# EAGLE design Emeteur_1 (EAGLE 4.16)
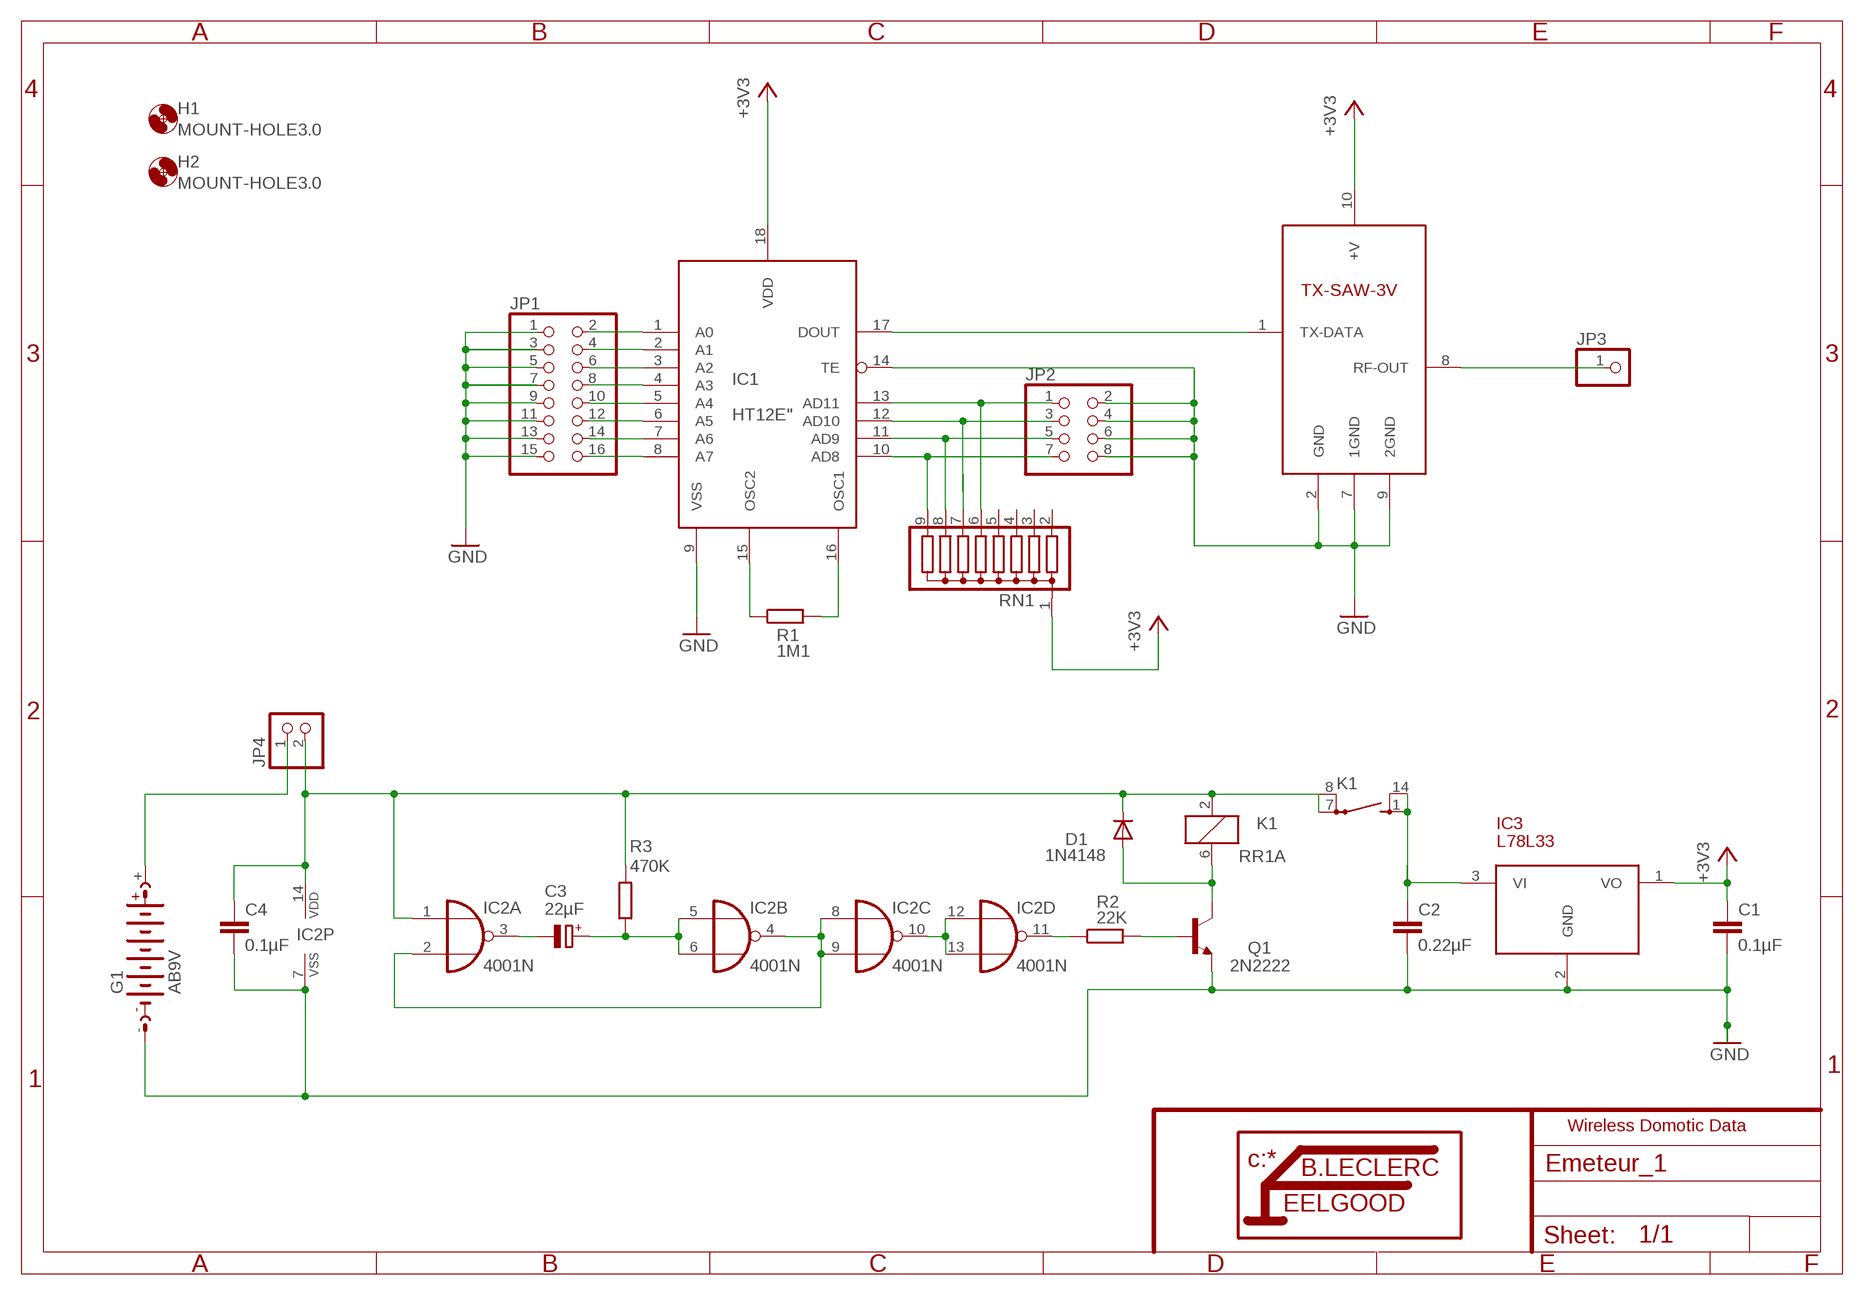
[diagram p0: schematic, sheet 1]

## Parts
C1  0.1µF  C-EU102-043X133  [C102-043X133]
C2  0.22µF  C-EU102-043X133  [C102-043X133]
C3  22µF  CPOL-EUE2.5-7  [E2,5-7]
C4  0.1µF  C-EU102-043X133  [C102-043X133]
D1  1N4148  [DO35-10]
G1  AB9V  [AB9V]
H1  MOUNT-HOLE3.0  [3,0]
H2  MOUNT-HOLE3.0  [3,0]
IC1  HT12E"  [18-DIP-A]
IC2  4001N  [DIL14]
IC3  L78L33  [TO92]
JP1  PINHD-2X8  [2X08]
JP2  PINHD-2X4  [2X04]
JP3  PINHD-1X1  [1X01]
JP4  PINHD-1X2  [1X02]
K1  RR1A  [RR1A]
Q1  2N2222  [TO18]
R1  1M1  R-EU_0207/10  [0207/10]
R2  22K  R-EU_0207/10  [0207/10]
R3  470K  R-EU_0207/10  [0207/10]
RN1  G08R  [SIL9]
TX-SAW1  AUREL_TX-SAW-3V  [AUREL_TX-SAW_3V]

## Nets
+3V3: C1.1 IC1.18(VDD) IC3.1(VO) RN1.1 TX-SAW1.10(+V)
GND: C1.2 C2.2 C4.2 G1.- IC1.9(VSS) IC1.14(TE) IC2.7(P:VSS) IC3.2(GND) JP1.1 JP1.3 JP1.5 JP1.7 JP1.9 JP1.11 JP1.13 JP1.15 JP2.2 JP2.4 JP2.6 JP2.8 Q1.1(E) TX-SAW1.2(GND) TX-SAW1.7(1GND) TX-SAW1.9(2GND)
N$1: JP3.1 TX-SAW1.8(RF-OUT)
N$2: IC1.13(AD11) JP2.1 RN1.6
N$3: IC1.17(DOUT) TX-SAW1.1(TX-DATA)
N$4: IC1.12(AD10) JP2.3 RN1.7
N$5: IC1.11(AD9) JP2.5 RN1.8
N$6: IC1.10(AD8) JP2.7 RN1.9
N$7: IC1.15(OSC2) R1.1
N$8: IC1.16(OSC1) R1.2
N$9: IC1.1(A0) JP1.2
N$10: IC1.2(A1) JP1.4
N$11: IC1.3(A2) JP1.6
N$12: IC1.4(A3) JP1.8
N$13: IC1.5(A4) JP1.10
N$14: IC1.6(A5) JP1.12
N$15: IC1.7(A6) JP1.14
N$16: IC1.8(A7) JP1.16
N$17: C2.1 IC3.3(VI) K1.1(2:S) K1.14(2:S)
N$18: G1.+ JP4.1
N$19: C3.- IC2.3(A:O)
N$20: D1.A K1.6 Q1.3(C)
N$21: Q1.2(B) R2.2
N$23: C3.+ IC2.5(B:I0) IC2.6(B:I1) R3.1
N$24: IC2.2(A:I1) IC2.4(B:O) IC2.8(C:I0) IC2.9(C:I1)
N$25: IC2.10(C:O) IC2.12(D:I0) IC2.13(D:I1)
N$27: IC2.11(D:O) R2.1
VDD: C4.1 D1.C IC2.1(A:I0) IC2.14(P:VDD) JP4.2 K1.2 K1.7(2:P) K1.8(2:P) R3.2
Unconnected: RN1.2 RN1.3 RN1.4 RN1.5

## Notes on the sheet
- Wireless Domotic Data

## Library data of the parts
C1 C2 C4 = rcl:C-EU: CAPACITOR, European symbol
C3 = rcl:CPOL-EU: POLARIZED CAPACITOR, European symbol
D1 = diode:1N4148: DIODE
G1 = battery:AB9V: 9-V BATTERY CLIP
H1 H2 = holes:MOUNT-HOLE: MOUNTING HOLE with drill center marker
IC1 = holtek:HT12E: transmitter = encoder ic
IC2 = 40xx:4001: Quad 2-input NOR
IC3 = linear:L78L33
JP1 = pinhead:PINHD-2X8: PIN HEADER
JP2 = pinhead:PINHD-2X4: PIN HEADER
JP3 = pinhead:PINHD-1X1: PIN HEADER
JP4 = pinhead:PINHD-1X2: PIN HEADER
K1 = relay:RR1A: RELAY reed, polarity, 1 x norm. open with shield
Q1 = transistor-npn:2N2222*: NPN Transistor
R1-R3 = rcl:R-EU_: RESISTOR, European symbol
RN1 = resistor-sil:G08R: SIL RESISTOR
TX-SAW1 = aurel:AUREL_TX-SAW-3V

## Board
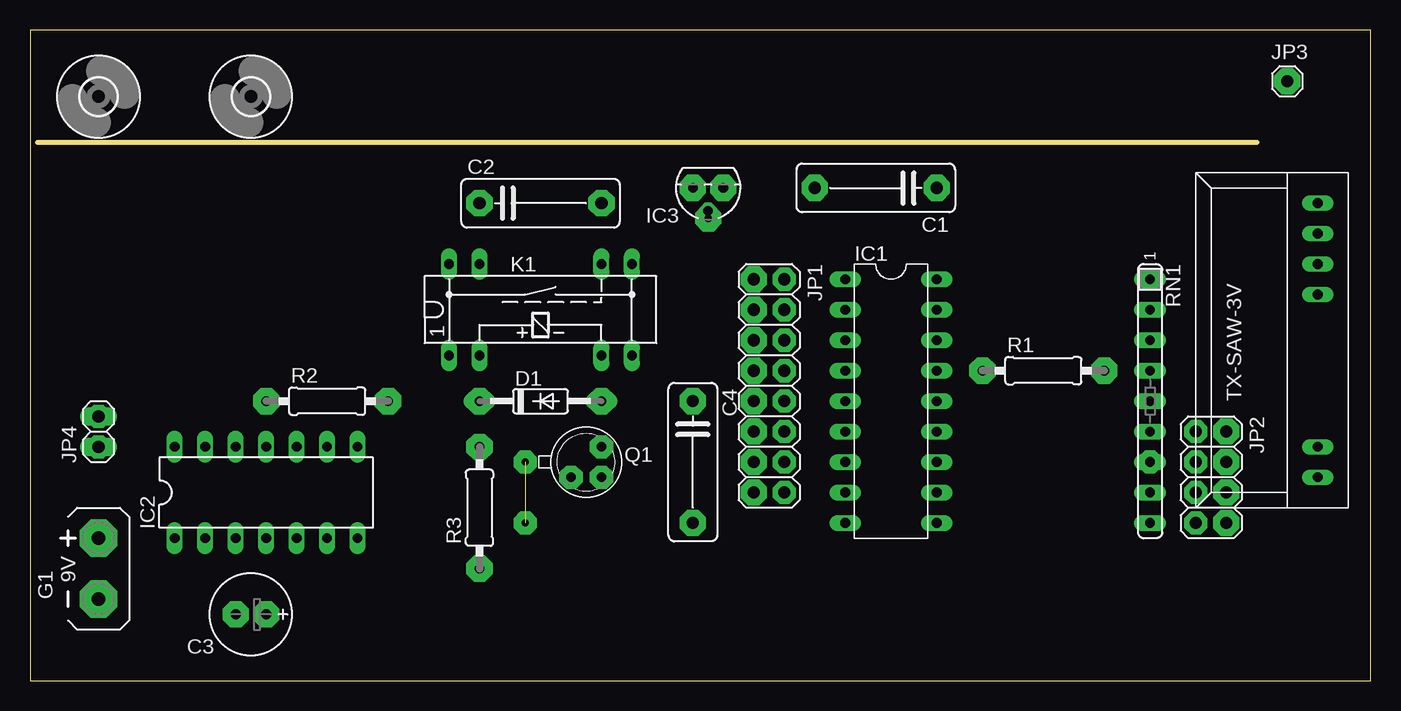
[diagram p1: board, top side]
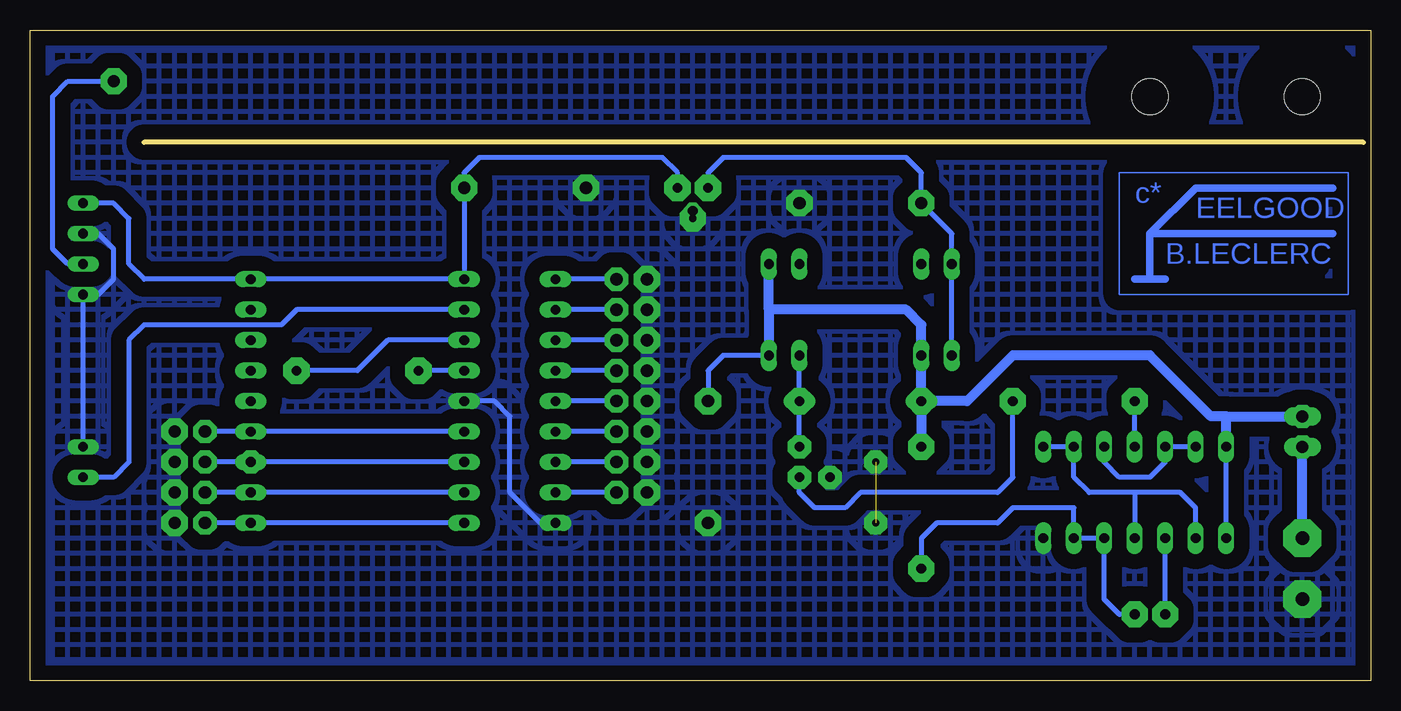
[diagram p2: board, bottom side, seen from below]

Size 111.74 x 54.28 mm. Coordinates in mm from the lower left corner, seen from the top.
Outline: 0.63,44.92 102.23,44.92
Outline: 0,0 111.74,0 111.74,54.28 0,54.28 0,0
Copper layers (1*16): Top 0.035mm / dielectric 1.5mm / Bottom 0.035mm
Design rules "default": minimum track width 10mil, minimum drill 24mil, track to track 8mil, track to pad 8mil, pad to pad 8mil, via to via 8mil, smd to smd 8mil, copper to edge 40mil, drill to drill 8mil, minimum pad ring 10mil, minimum via ring 8mil, stop-mask expansion 4mil, vias tented up to drill 0mil, thermal gap 10mil

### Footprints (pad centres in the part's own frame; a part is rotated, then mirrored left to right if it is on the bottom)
C102-043X133 = drill 1.016 octagon: 1 -5.08,0; 2 5.08,0
E2,5-7 = drill 0.813 pad 1.6 round: + -1.27,0 | drill 0.813 pad 1.6 octagon: - 1.27,0
DO35-10 = drill 0.813 long: A 5.08,0; C -5.08,0
AB9V = drill 1.118 pad 3.15 octagon: + 0,2.54; - 0,-2.54
3,0 = hole 3: 0,0
18-DIP-A = drill 0.813 long: 1 -10.16,-3.81; 2 -7.62,-3.81; 3 -5.08,-3.81; 4 -2.54,-3.81; 5 0,-3.81; 6 2.54,-3.81; 7 5.08,-3.81; 8 7.62,-3.81; 9 10.16,-3.81; 10 10.16,3.81; 11 7.62,3.81; 12 5.08,3.81; 13 2.54,3.81; 14 0,3.81; 15 -2.54,3.81; 16 -5.08,3.81; 17 -7.62,3.81; 18 -10.16,3.81
DIL14 = drill 0.813 long: 1 -7.62,-3.81; 2 -5.08,-3.81; 3 -2.54,-3.81; 4 0,-3.81; 5 2.54,-3.81; 6 5.08,-3.81; 7 7.62,-3.81; 8 7.62,3.81; 9 5.08,3.81; 10 2.54,3.81; 11 0,3.81; 12 -2.54,3.81; 13 -5.08,3.81; 14 -7.62,3.81
TO92 = drill 0.813 octagon: 1 -1.27,0; 2 0,1.905; 3 1.27,0
2X08 = drill 1.016 octagon: 1 -8.89,-1.27; 2 -8.89,1.27; 3 -6.35,-1.27; 4 -6.35,1.27; 5 -3.81,-1.27; 6 -3.81,1.27; 7 -1.27,-1.27; 8 -1.27,1.27; 9 1.27,-1.27; 10 1.27,1.27; 11 3.81,-1.27; 12 3.81,1.27; 13 6.35,-1.27; 14 6.35,1.27; 15 8.89,-1.27; 16 8.89,1.27
2X04 = drill 1.016 octagon: 1 -3.81,-1.27; 2 -3.81,1.27; 3 -1.27,-1.27; 4 -1.27,1.27; 5 1.27,-1.27; 6 1.27,1.27; 7 3.81,-1.27; 8 3.81,1.27
1X01 = drill 1.016 octagon: 1 0,0
1X02 = drill 1.016 long: 1 -1.27,0; 2 1.27,0
RR1A = drill 0.813 long: 1 -7.62,-3.81; 2 -5.08,-3.81; 6 5.08,-3.81; 7 7.62,-3.81; 8 7.62,3.81; 9 5.08,3.81; 13 -5.08,3.81; 14 -7.62,3.81
TO18 = drill 0.813 octagon: 1 -1.27,-1.27; 2 1.27,-1.27; 3 1.27,1.27
0207/10 = drill 0.813 octagon: 1 -5.08,0; 2 5.08,0
SIL9 = drill 0.813 long: 1 -10.16,0; 2 -7.62,0; 3 -5.08,0; 4 -2.54,0; 5 0,0; 6 2.54,0; 7 5.08,0; 8 7.62,0; 9 10.16,0
AUREL_TX-SAW_3V = drill 0.8 long: 1 -10.16,0; 2 -7.62,0; 7 5.08,0; 8 7.62,0; 9 10.16,0; 10 12.7,0

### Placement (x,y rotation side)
C1  70.48,41.11 180 top
C2  42.54,39.84 0 top
C3  18.41,5.55 180 top
C4  55.24,18.25 270 top
D1  42.54,23.33 0 top
G1  5.71,9.36 0 top
H1  5.71,48.73 0 top
H2  18.41,48.73 0 top
IC1  71.75,23.33 270 top
IC2  19.68,15.71 0 top
IC3  56.51,41.11 180 top
JP1  61.59,24.6 270 top
JP2  98.42,16.98 270 top
JP3  104.77,50 0 top
JP4  5.71,20.79 90 top
K1  42.54,30.95 0 top
Q1  46.35,18.25 0 top
R1  84.45,25.87 0 top
R2  24.76,23.33 0 top
R3  37.46,14.44 90 top
RN1  93.34,23.33 270 top
TX-SAW1  107.31,27.14 90 top
U$2  [LITTFEEL]  18.41,29.68 0 bottom

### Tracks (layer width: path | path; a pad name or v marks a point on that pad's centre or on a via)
+3V3
  Bottom 0.406: TX-SAW1.10 104.77,39.84 103.5,38.57 103.5,34.76 102.23,33.49 RN1.1 IC1.18 C1.1 75.56,42.38 74.29,43.65 59.05,43.65 57.78,42.38 IC3.1
GND  (via drill 0.6 pad 1.93, 0.6 pad 2.18)  (1 unrouted)
  Bottom 0.406: IC1.14 73.02,23.33 71.75,22.06 71.75,15.71 69.21,13.17 IC1.9 | TX-SAW1.9 106.04,37.3 104.77,36.03 104.77,33.49 106.04,32.22 TX-SAW1.7 TX-SAW1.2
  other vias: 55.24,13.17 60.32,15.71 60.32,18.25 60.32,20.79 60.32,23.33 60.32,25.87 60.32,28.41 60.32,30.95 60.32,33.49 56.51,38.57 65.4,41.11 47.62,39.84 99.69,20.79 99.69,18.25 99.69,15.71 99.69,13.17 41.27,18.25 41.27,13.17 45.08,16.98
  pour Bottom (isolate 1.27, no thermals, hatched): 0.63,43.65 111.12,43.65 111.12,0.47 0.63,0.47
N$1
  Bottom 0.406: TX-SAW1.8 108.58,34.76 109.85,36.03 109.85,48.73 108.58,50 JP3.1
N$2
  Bottom 0.406: IC1.13 RN1.6 JP2.1
N$3
  Bottom 0.406: IC1.17 89.53,30.95 90.8,29.68 102.23,29.68 103.5,28.41 103.5,18.25 104.77,16.98 TX-SAW1.1
N$4
  Bottom 0.406: IC1.12 RN1.7 JP2.3
N$5
  Bottom 0.406: IC1.11 RN1.8 JP2.5
N$6
  Bottom 0.406: IC1.10 RN1.9 JP2.7
N$7
  Bottom 0.406: IC1.15 R1.1
N$8
  Bottom 0.406: IC1.16 81.91,28.41 84.45,25.87 R1.2
N$9
  Bottom 0.406: JP1.2 IC1.1
N$10
  Bottom 0.406: JP1.4 IC1.2
N$11
  Bottom 0.406: JP1.6 IC1.3
N$12
  Bottom 0.406: JP1.8 IC1.4
N$13
  Bottom 0.406: JP1.10 IC1.5
N$14
  Bottom 0.406: JP1.12 IC1.6
N$15
  Bottom 0.406: JP1.14 IC1.7
N$16
  Bottom 0.406: JP1.16 IC1.8
N$17
  Bottom 0.406: IC3.3 55.24,42.38 53.97,43.65 38.73,43.65 37.46,42.38 C2.1 34.92,37.3 K1.14 K1.1
N$18
  Bottom 0.813: G1.+ JP4.1
N$19
  Bottom 0.406: C3.- IC2.3
N$20
  Bottom 0.406: Q1.3 D1.A K1.6
N$21
  Bottom 0.406: R2.2 29.84,16.98 31.11,15.71 42.54,15.71 43.81,14.44 46.35,14.44 47.62,15.71 Q1.2
N$22  (via drill 0.6 pad 2.18)
  other vias: 37.46,39.84
N$23
  Bottom 0.406: C3.+ 20.95,5.55 22.22,6.82 IC2.5 IC2.6 24.76,14.44 29.84,14.44 31.11,13.17 36.19,13.17 37.46,11.9 R3.1
N$24
  Bottom 0.406: IC2.8 IC2.9 24.76,16.98 23.49,15.71 19.68,15.71 | IC2.2 14.6,14.44 15.87,15.71 19.68,15.71 | 19.68,15.71 IC2.4
N$25
  Bottom 0.406: IC2.13 IC2.12 17.14,18.25 18.41,16.98 20.95,16.98 22.22,18.25 IC2.10
N$26
  pour Bottom (isolate 1.27, no thermals, hatched): 0.63,1.74 0.63,53.81 111.12,53.81 111.12,0.47 0.63,0.47
N$27
  Bottom 0.406: IC2.11 R2.1
N$28  (via drill 0.6 pad 2.18)
  other vias: 55.24,41.11
N$29  (via drill 0.6 pad 2.18)
  other vias: 57.78,41.11
N$30  (via drill 0.6 pad 1.93)
  other vias: 47.62,16.98
N$31  (via drill 0.6 pad 1.93)
  other vias: 47.62,19.52
N$32  (via drill 0.6 pad 2.18)
  other vias: 75.56,41.11
N$33  (via drill 0.6 pad 2.18)
  other vias: 79.37,25.87
N$34  (via drill 0.6 pad 2.18)
  other vias: 89.53,25.87
N$36  (via drill 0.6 pad 2.18)
  other vias: 104.77,50
N$43  (via drill 0.6 pad 2.18)
  other vias: 17.14,5.55
N$44  (via drill 0.6 pad 2.18)
  other vias: 19.68,5.55
N$45  (via drill 0.6 pad 2.18)
  other vias: 19.68,23.33
N$46  (via drill 0.6 pad 2.18)
  other vias: 37.46,19.52
N$47  (via drill 0.6 pad 2.18)
  other vias: 29.84,23.33
N$48  (via drill 0.6 pad 2.18)
  other vias: 37.46,9.36
N$49  (via drill 0.6 pad 2.18)
  other vias: 37.46,23.33
N$50  (via drill 0.6 pad 2.18)
  other vias: 47.62,23.33
N$52  (via drill 0.6 pad 2.18)
  other vias: 55.24,23.33
N$54  (via drill 0.6 pad 1.93)
  other vias: 5.71,19.52
N$55  (via drill 0.6 pad 1.93)
  other vias: 5.71,22.06
N$64  (via drill 0.6 pad 1.93)
  other vias: 97.15,13.17
N$65  (via drill 0.6 pad 1.93)
  other vias: 97.15,15.71
N$66  (via drill 0.6 pad 1.93)
  other vias: 93.34,18.25
N$67  (via drill 0.6 pad 1.93)
  other vias: 97.15,18.25
N$68  (via drill 0.6 pad 1.93)
  other vias: 97.15,20.79
N$69  (via drill 0.6 pad 1.93)
  other vias: 62.86,15.71
N$70  (via drill 0.6 pad 1.93)
  other vias: 62.86,18.25
N$71  (via drill 0.6 pad 1.93)
  other vias: 62.86,20.79
N$72  (via drill 0.6 pad 1.93)
  other vias: 62.86,23.33
N$73  (via drill 0.6 pad 1.93)
  other vias: 62.86,25.87
N$74  (via drill 0.6 pad 1.93)
  other vias: 62.86,28.41
N$75  (via drill 0.6 pad 1.93)
  other vias: 62.86,30.95
N$76  (via drill 0.6 pad 1.93)
  other vias: 62.86,33.49
VDD
  Bottom 0.406: K1.7 53.97,27.14 55.24,25.87 C4.1 | IC2.1 IC2.14
  Bottom 0.813: 50.16,30.95 K1.7 | 50.16,30.95 K1.8 | 50.16,30.95 38.73,30.95 37.46,29.68 K1.2 D1.C | D1.C R3.2 | 12.06,22.06 JP4.2 | IC2.14 12.06,22.06 | 12.06,22.06 13.33,22.06 18.41,27.14 29.84,27.14 33.65,23.33 D1.C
